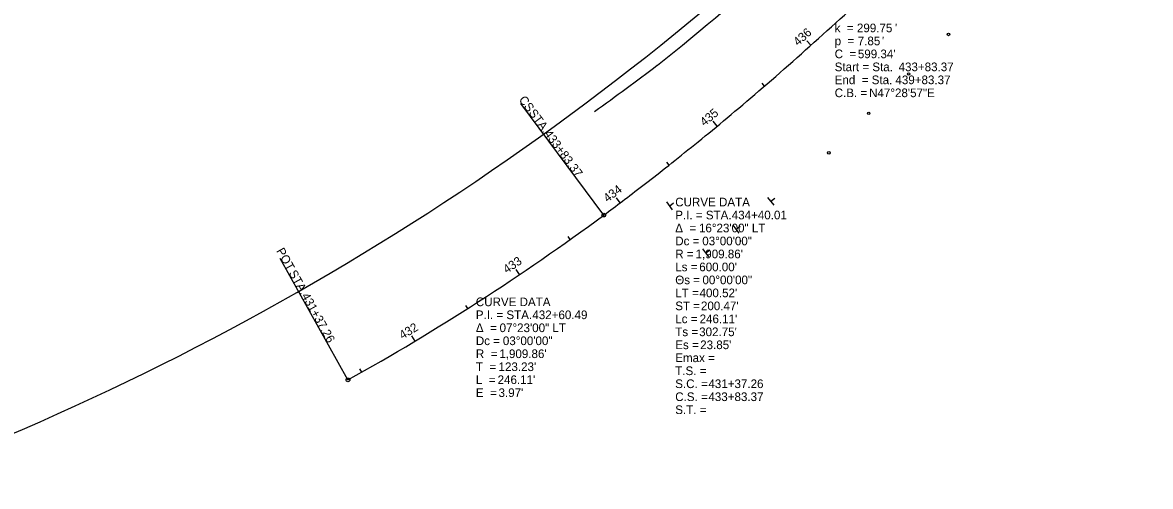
# Model space of a CAD drawing. Extents: x 142554 to 147512, y 370190 to 373751.
# Drawn here: x 143465 to 144376, y 370478 to 370854 of the extents above; entities that cross this region are included whole.
import ezdxf

# ---------------------------------------------------------------- set-up
doc = ezdxf.new("R2010")
doc.units = 0
for name, color, linetype in [('DR_X_GenericNode', 7, 'Continuous'), ('FeatureService_Stream Network', 7, 'Continuous'), ('PM_X_Channelizing_Line', 7, 'Continuous'), ('PM_X_Edge_Line', 7, 'Continuous'), ('PM_X_Transverse_Line', 7, 'Continuous'), ('RD_X_GR_Cable_Bar', 7, 'Continuous'), ('RD_X_GR_Lt', 7, 'Continuous'), ('SC_Scratch20', 7, 'Continuous')]:
    doc.layers.add(name, color=color, linetype=linetype)

msp = doc.modelspace()

# ---------------------------------------------------------------- linework, layer by layer
at = {"layer": 'DR_X_GenericNode'}
for centre, radius, start, end in [((142449.76, 372731.46), 2447.92, 308.62472, 315.1207), ((142613.19, 372620.55), 2260, 305.54599, 307.14268)]:
    msp.add_arc(centre, radius, start, end, dxfattribs=at)
at = {"layer": 'FeatureService_Stream Network'}
for centre in [(144213.04, 370843.93), (144180.82, 370812.01), (144148.61, 370780.08), (144116.39, 370748.16)]:
    msp.add_circle(centre, 1, dxfattribs=at)
at = {"layer": 'PM_X_Channelizing_Line'}
for p, q in [((143934.48, 370697.77), (143867.53, 370788.18)), ((143727.81, 370564.45), (143673.04, 370662.72))]:
    msp.add_line(p, q, dxfattribs=at)
for centre in [(143934.48, 370697.77), (143727.81, 370564.45)]:
    msp.add_circle(centre, 1.5, dxfattribs=at)
at = {"layer": 'PM_X_Edge_Line'}
msp.add_arc((142798, 372232.69), 1909.86, 299.1336, 306.5169, dxfattribs=at)
msp.add_open_spline([(143934.48, 370697.77), (143944.52, 370705.21), (143964.47, 370720.28), (144003.8, 370751.16), (144051.95, 370791.01), (144108.31, 370840.51), (144163.42, 370891.38), (144217.53, 370943.32), (144270.87, 370996.05), (144314.88, 371040.43), (144349.96, 371076.06), (144367.48, 371093.89), (144376.23, 371102.81)], degree=3, dxfattribs=at)
at = {"layer": 'RD_X_GR_Cable_Bar'}
for p, q in [((144101.87, 370835.15), (144098.54, 370838.87)), ((144064.33, 370802.12), (144062.37, 370804.39)), ((144026.18, 370769.81), (144022.99, 370773.66)), ((143987.35, 370738.31), (143985.49, 370740.66)), ((143947.8, 370707.72), (143944.79, 370711.71)), ((143907.49, 370678.15), (143905.74, 370680.59)), ((143866.41, 370649.63), (143863.62, 370653.78)), ((143824.61, 370622.21), (143822.99, 370624.74)), ((143782.1, 370595.89), (143779.52, 370600.17)), ((143738.91, 370570.69), (143737.44, 370573.3))]:
    msp.add_line(p, q, dxfattribs=at)
at = {"layer": 'RD_X_GR_Lt'}
for p, q in [((144072.19, 370705.9), (144067.05, 370712.04)), ((144069.62, 370708.97), (144072.69, 370711.53)), ((143990.18, 370702.09), (143985.35, 370708.47)), ((143987.77, 370705.28), (143990.95, 370707.7)), ((143987.77, 370705.28), (143987.77, 370705.28)), ((144069.62, 370708.97), (144069.62, 370708.97)), ((144043.91, 370683.16), (144039.05, 370689.51)), ((144041.48, 370686.34), (144044.65, 370688.77)), ((144041.48, 370686.33), (144041.48, 370686.33)), ((144019.5, 370664.08), (144014.66, 370670.46)), ((144017.08, 370667.27), (144020.27, 370669.69)), ((144017.08, 370667.27), (144017.08, 370667.27))]:
    msp.add_line(p, q, dxfattribs=at)
at = {"layer": 'SC_Scratch20'}
msp.add_arc((142571.53, 372589.5), 2250, 290.2255, 315.49226, dxfattribs=at)

# ---------------------------------------------------------------- texts
at = {"layer": 'PM_X_Channelizing_Line'}
for s, rotation, p in [('CS', 306.5169, (143865.51, 370791.09)), (' STA. ', 306.5169, (143871.9, 370782.45)), ('433+83.37', 306.5169, (143885.97, 370763.46)), ('POT', 299.1336, (143669.71, 370668.9)), (' STA. ', 299.1336, (143678.47, 370653.18)), ('431+37.26', 299.1336, (143689.97, 370632.54))]:
    msp.add_text(s, height=7, rotation=rotation, dxfattribs=at).set_placement(p)
at = {"layer": 'PM_X_Transverse_Line'}
for s, p in [('k  = ', (144121.09, 370845.7)), ('299.75', (144139.07, 370845.7)), ("'", (144169.79, 370845.7)), ('p  = ', (144121.09, 370835.2)), ('7.85', (144139.73, 370835.2)), ("'", (144159.27, 370835.2)), ('C  = ', (144121.09, 370824.7)), ("599.34'", (144139.82, 370824.7)), ('Start = Sta. ', (144121.09, 370814.2)), ('433+83.37', (144172.72, 370814.2)), ('End  = Sta. ', (144121.09, 370803.7)), ('439+83.37', (144170.17, 370803.7)), ('C.B. = ', (144121.09, 370793.2)), ('N47°28\'57"E', (144148.9, 370793.2)), ('CURVE DATA', (143992.26, 370704.84)), ('P.I. = STA. ', (143992.26, 370694.34)), ('434+40.01', (144037.92, 370694.34)), ('Δ  = ', (143992.26, 370683.84)), ('16°23\'00" LT', (144011.45, 370683.84)), ('Dc = ', (143992.26, 370673.34)), ('03°00\'00"', (144014.1, 370673.34)), ('R = ', (143992.26, 370662.84)), ("1,909.86'", (144008.72, 370662.84)), ('Ls = ', (143992.26, 370652.34)), ("600.00'", (144011.66, 370652.34)), ('Θs = ', (143992.26, 370641.84)), ('00°00\'00"', (144014.26, 370641.84)), ('CURVE DATA', (143831.14, 370624.11)), ('LT = ', (143992.26, 370631.34)), ("400.52'", (144011.89, 370631.34)), ('P.I. = STA. ', (143831.14, 370613.61)), ('432+60.49', (143876.81, 370613.61)), ('ST = ', (143992.26, 370620.84)), ("200.47'", (144013.03, 370620.84)), ('Lc = ', (143992.26, 370610.34)), ("246.11'", (144011.95, 370610.34)), ('Δ  = ', (143831.14, 370603.11)), ('07°23\'00" LT', (143850.33, 370603.11)), ('Ts = ', (143992.26, 370599.84)), ("302.75'", (144011.59, 370599.84)), ('Dc = ', (143831.14, 370592.61)), ('03°00\'00"', (143852.99, 370592.61)), ('Es = ', (143992.26, 370589.34)), ("23.85'", (144012.41, 370589.34)), ('R  = ', (143831.14, 370582.11)), ("1,909.86'", (143850.1, 370582.11)), ('Emax = ', (143992.26, 370578.84)), ('T  = ', (143831.14, 370571.61)), ("123.23'", (143849.49, 370571.61)), ('T.S. = ', (143992.26, 370568.34)), ('L  = ', (143831.14, 370561.11)), ("246.11'", (143848.74, 370561.11)), ('E  = ', (143831.14, 370550.61)), ("3.97'", (143849.49, 370550.61)), ('S.C. = ', (143992.26, 370557.84)), ('431+37.26', (144019.06, 370557.84)), ('C.S. = ', (143992.26, 370547.34)), ('433+83.37', (144019.06, 370547.34)), ('S.T. = ', (143992.26, 370536.84))]:
    msp.add_text(s, height=7, dxfattribs=at).set_placement(p)
at = {"layer": 'RD_X_GR_Cable_Bar'}
for s, rotation, p in [('436', 41.84258, (144091.45, 370834.2)), ('435', 39.67574, (144015.83, 370769.34)), ('434', 37.00889, (143937.5, 370707.79)), ('433', 34.0158, (143856.14, 370650.24)), ('432', 31.0158, (143771.85, 370597.02))]:
    msp.add_text(s, height=7, rotation=rotation, dxfattribs=at).set_placement(p)

doc.saveas('drawing.dxf')
